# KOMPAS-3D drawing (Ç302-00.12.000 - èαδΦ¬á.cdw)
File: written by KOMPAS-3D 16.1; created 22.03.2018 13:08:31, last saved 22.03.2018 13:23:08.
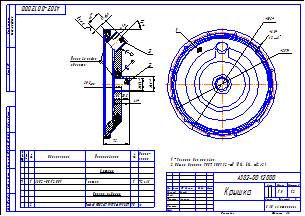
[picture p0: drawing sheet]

Sheet 1: A3, landscape

Title block, sheet 1: name: Крышка; designation: А302-00.12.000; mass: 1,5; scale: 1:2; sheets: 1; organisation: ЗАО «Астерион»; sheet format: A3; stored path: Z:\Мембранные насосы\Мембранный электропривод\А302-00.00.000 - ASTRA-302 (МЭ200)\Чертежи\А302-00.12.000 - Крышка.cdw; drawn by: Милов; technical control: Лучихин

Views: Вид 1, Местный разрез 1, Вид:1, Проекционный вид 2
Referenced files in Z:\1 ПКИ 3D\Полипропиленовые фитинги, трубы\: Труба ф40х3,7 (PN10) FV PPR ф. FV PLAST.m3d
Referenced files in Z:\Мембранные насосы\Мембранный электропривод\А302-00.00.000 - ASTRA-302 (МЭ200)\3Д\: А302-00.12.001 - Крышка.m3d, А302-00.12.000 - Крышка.a3d
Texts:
  Наплывы пайки
  удалить
  Ra 3,2
  *Размеры для справок.
  Общие допуски ГОСТ 30893.2-mK (H14, h14,  t2/2).
  Труба ф40х3,7 (PN10) FV PPR ф. FV PLAST
Dimensions and other numbers on the sheet: 19,5; 20,5; 21,5; 41; 32,6; 40; 2; 72; 302; 6,5; 12 отв.; 1; 287; 1:2; 1,5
